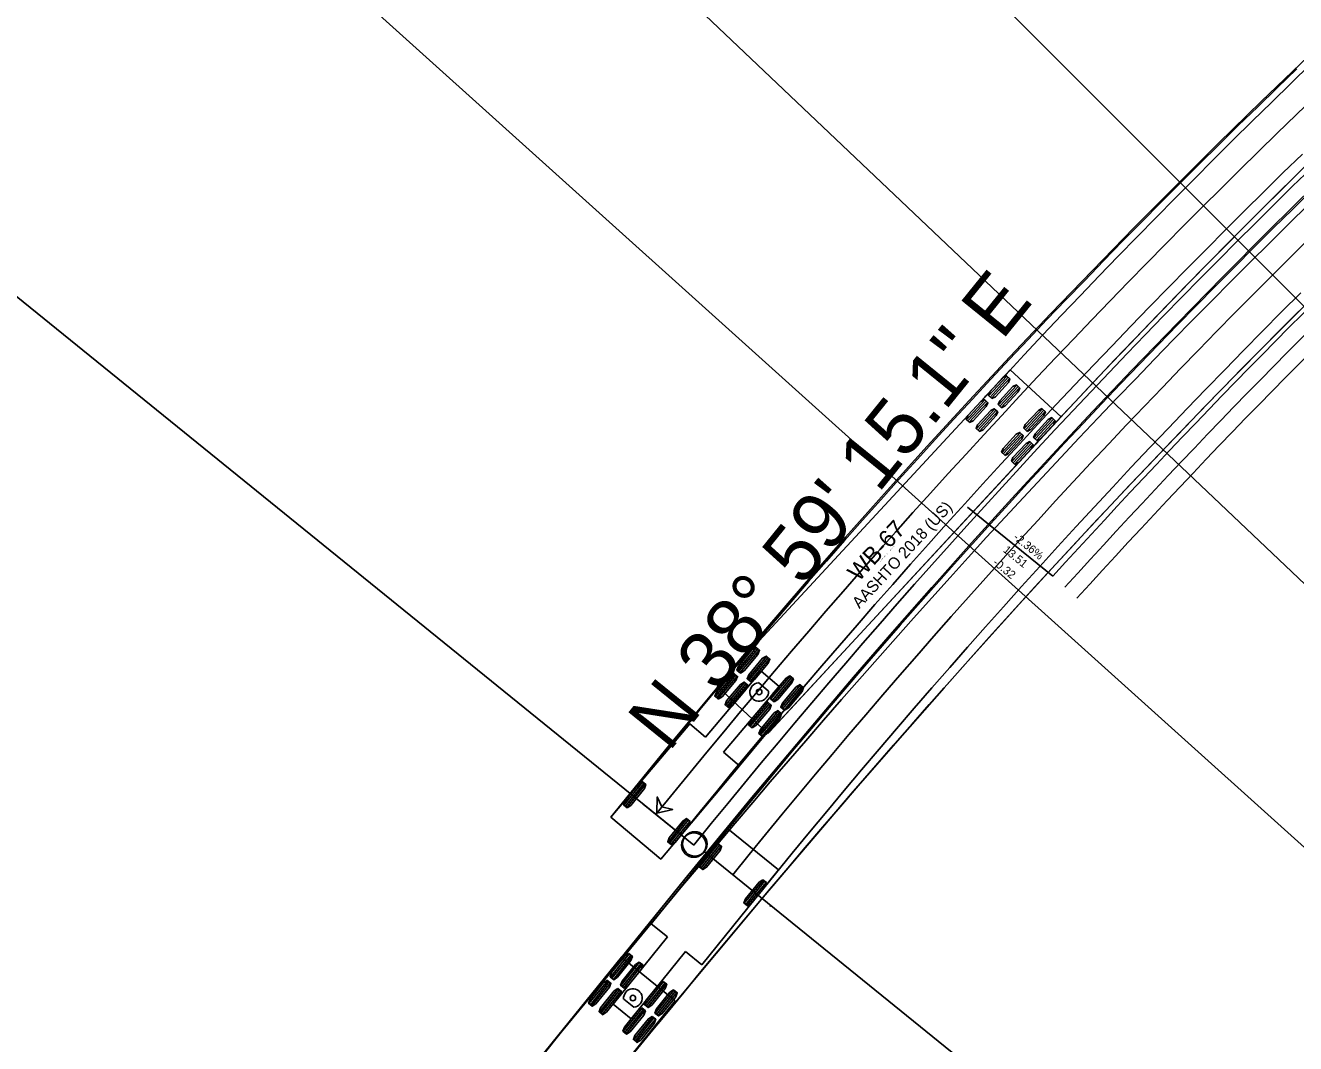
# Model space of a CAD drawing. Extents: x 2293233 to 2294507, y 892788 to 894229.
# Drawn here: x 2293388.7 to 2293544.7, y 893014 to 893139.1 of the extents above; entities that cross this region are included whole.
import ezdxf

# ---------------------------------------------------------------- set-up
doc = ezdxf.new("R2010")
doc.units = 0
for name, color, linetype in [('COGO Default Curve', 7, 'Continuous'), ('Default', 7, 'Continuous'), ('Prop EOT', 7, 'Continuous'), ('Prop Horizontal Alignment', 7, 'Continuous'), ('Prop Paved Shoulder', 7, 'Continuous'), ('Scratch_Level_4', 7, 'Continuous'), ('Scratch_Level_5', 7, 'Continuous'), ('Scratch_Level_6', 7, 'Continuous')]:
    doc.layers.add(name, color=color, linetype=linetype)

msp = doc.modelspace()

# ---------------------------------------------------------------- linework, layer by layer
at = {"layer": 'COGO Default Curve'}
for p, q in [((2293509.68, 893096.77), (2293473.68, 893057.88)), ((2293507.03, 893093.57), (2293509.27, 893095.99)), ((2293515.92, 893091), (2293509.68, 893096.77)), ((2293507.2, 893093.41), (2293509.44, 893095.84)), ((2293507.37, 893093.26), (2293509.61, 893095.68)), ((2293508.24, 893092.45), (2293510.48, 893094.87)), ((2293508.41, 893092.29), (2293510.65, 893094.72)), ((2293508.58, 893092.14), (2293510.82, 893094.56)), ((2293504.31, 893090.63), (2293506.55, 893093.06)), ((2293504.48, 893090.48), (2293506.72, 893092.9)), ((2293504.65, 893090.32), (2293506.89, 893092.75)), ((2293505.52, 893089.51), (2293507.76, 893091.94)), ((2293505.69, 893089.36), (2293507.93, 893091.78)), ((2293505.86, 893089.2), (2293508.1, 893091.62)), ((2293511.38, 893089.54), (2293513.63, 893091.96)), ((2293511.55, 893089.38), (2293513.79, 893091.81)), ((2293511.72, 893089.23), (2293513.96, 893091.65)), ((2293479.91, 893052.1), (2293515.92, 893091)), ((2293512.59, 893088.42), (2293514.84, 893090.84)), ((2293512.76, 893088.26), (2293515, 893090.68)), ((2293512.93, 893088.11), (2293515.17, 893090.53)), ((2293508.67, 893086.6), (2293510.91, 893089.03)), ((2293508.83, 893086.45), (2293511.08, 893088.87)), ((2293509, 893086.29), (2293511.24, 893088.71)), ((2293509.88, 893085.48), (2293512.12, 893087.9)), ((2293510.05, 893085.33), (2293512.29, 893087.75)), ((2293510.21, 893085.17), (2293512.46, 893087.59)), ((2293476.12, 893059.83), (2293478.49, 893062.63)), ((2293476.3, 893059.68), (2293478.66, 893062.48)), ((2293476.47, 893059.53), (2293478.84, 893062.33)), ((2293477.38, 893058.76), (2293479.75, 893061.57)), ((2293477.56, 893058.62), (2293479.92, 893061.42)), ((2293477.73, 893058.47), (2293480.1, 893061.27)), ((2293479.09, 893059.72), (2293472.25, 893051.62)), ((2293473.41, 893056.62), (2293475.78, 893059.42)), ((2293473.59, 893056.47), (2293475.95, 893059.27)), ((2293473.76, 893056.32), (2293476.13, 893059.13)), ((2293481.28, 893057.87), (2293479.09, 893059.72)), ((2293480.28, 893056.32), (2293482.64, 893059.13)), ((2293480.45, 893056.18), (2293482.82, 893058.98)), ((2293480.63, 893056.03), (2293482.99, 893058.83)), ((2293473.68, 893057.88), (2293479.91, 893052.1)), ((2293474.45, 893049.77), (2293481.28, 893057.87)), ((2293474.68, 893055.55), (2293477.04, 893058.36)), ((2293474.85, 893055.41), (2293477.22, 893058.21)), ((2293475.03, 893055.26), (2293477.39, 893058.06)), ((2293479.97, 893057.29), (2293478.74, 893058.33)), ((2293481.54, 893055.26), (2293483.9, 893058.06)), ((2293481.71, 893055.11), (2293484.08, 893057.91)), ((2293481.89, 893054.96), (2293484.25, 893057.77)), ((2293477.57, 893053.11), (2293479.93, 893055.92)), ((2293477.74, 893052.97), (2293480.11, 893055.77)), ((2293477.92, 893052.82), (2293480.28, 893055.62)), ((2293478.83, 893052.05), (2293481.19, 893054.85)), ((2293479, 893051.9), (2293481.37, 893054.7)), ((2293479.18, 893051.75), (2293481.54, 893054.56)), ((2293470.29, 893053.28), (2293460.62, 893041.81)), ((2293472.25, 893051.62), (2293470.29, 893053.28)), ((2293479.91, 893052.1), (2293479.91, 893052.1)), ((2293476.41, 893048.12), (2293474.45, 893049.77)), ((2293466.73, 893036.65), (2293476.41, 893048.12)), ((2293462.21, 893043.29), (2293464.52, 893046.14)), ((2293462.39, 893043.14), (2293464.7, 893045.99)), ((2293462.57, 893043), (2293464.87, 893045.85)), ((2293460.62, 893041.81), (2293466.73, 893036.65)), ((2293467.64, 893038.73), (2293469.94, 893041.58)), ((2293467.81, 893038.59), (2293470.12, 893041.44)), ((2293474.99, 893040.37), (2293465.55, 893028.71)), ((2293467.99, 893038.44), (2293470.3, 893041.29)), ((2293481.21, 893035.33), (2293474.99, 893040.37)), ((2293474.99, 893040.37), (2293474.99, 893040.37)), ((2293473.81, 893038.54), (2293471.5, 893035.69)), ((2293473.98, 893038.39), (2293471.68, 893035.54)), ((2293474.16, 893038.25), (2293471.85, 893035.4)), ((2293466.73, 893036.65), (2293466.73, 893036.65)), ((2293471.77, 893023.67), (2293481.21, 893035.33)), ((2293479.31, 893034.08), (2293477, 893031.23)), ((2293479.49, 893033.94), (2293477.18, 893031.09)), ((2293479.67, 893033.79), (2293477.36, 893030.94)), ((2293465.55, 893028.71), (2293467.55, 893027.09)), ((2293467.55, 893027.09), (2293460.88, 893018.85)), ((2293461.9, 893024.59), (2293428.55, 892983.39)), ((2293462.86, 893025.01), (2293460.55, 893022.16)), ((2293463.04, 893024.87), (2293460.73, 893022.02)), ((2293463.21, 893024.73), (2293460.91, 893021.88)), ((2293468.51, 893019.24), (2293461.9, 893024.59)), ((2293461.9, 893024.59), (2293461.9, 893024.59)), ((2293463.11, 893017.05), (2293469.78, 893025.29)), ((2293469.78, 893025.29), (2293471.77, 893023.67)), ((2293464.14, 893023.98), (2293461.83, 893021.13)), ((2293464.32, 893023.83), (2293462.01, 893020.98)), ((2293464.5, 893023.69), (2293462.19, 893020.84)), ((2293460.22, 893021.75), (2293457.91, 893018.9)), ((2293460.39, 893021.61), (2293458.09, 893018.76)), ((2293460.57, 893021.46), (2293458.26, 893018.61)), ((2293467.08, 893021.6), (2293464.77, 893018.75)), ((2293467.26, 893021.45), (2293464.95, 893018.6)), ((2293467.44, 893021.31), (2293465.13, 893018.46)), ((2293461.5, 893020.71), (2293459.19, 893017.86)), ((2293461.68, 893020.57), (2293459.37, 893017.72)), ((2293461.85, 893020.42), (2293459.55, 893017.57)), ((2293468.36, 893020.56), (2293466.06, 893017.71)), ((2293468.54, 893020.41), (2293466.23, 893017.56)), ((2293468.72, 893020.27), (2293466.41, 893017.42)), ((2293435.16, 892978.05), (2293468.51, 893019.24)), ((2293460.88, 893018.85), (2293463.11, 893017.05)), ((2293464.44, 893018.33), (2293462.13, 893015.48)), ((2293462.18, 893019.46), (2293463.43, 893018.45)), ((2293464.62, 893018.19), (2293462.31, 893015.34)), ((2293464.79, 893018.04), (2293462.49, 893015.19)), ((2293465.72, 893017.29), (2293463.41, 893014.44)), ((2293465.9, 893017.15), (2293463.59, 893014.3)), ((2293466.08, 893017), (2293463.77, 893014.15))]:
    msp.add_line(p, q, dxfattribs=at)
for points in [[(2293545.92, 893121.77), (2293541.18, 893117.08), (2293536.48, 893112.36), (2293531.8, 893107.6), (2293527.16, 893102.82), (2293522.55, 893098.01), (2293518.19, 893093.41), (2293513.42, 893088.3), (2293480.12, 893052.32), (2293479.78, 893052.17), (2293476.37, 893048.07), (2293466.73, 893036.65), (2293460.62, 893041.81), (2293462.02, 893043.56), (2293467.91, 893050.79), (2293473.66, 893057.7), (2293473.8, 893058.02), (2293479.39, 893064.63), (2293484.4, 893070.43), (2293489.44, 893076.2), (2293494.54, 893081.92), (2293499.46, 893087.36), (2293504.64, 893093), (2293509.64, 893098.36), (2293514.68, 893103.68), (2293519.77, 893108.97), (2293524.89, 893114.21), (2293530.06, 893119.42), (2293535.27, 893124.58), (2293540.51, 893129.71), (2293548.21, 893137.09)], [(2293544.9, 893133.73), (2293542.49, 893131.41), (2293540.09, 893129.08), (2293537.69, 893126.75), (2293535.31, 893124.4), (2293532.93, 893122.05), (2293530.56, 893119.69), (2293528.19, 893117.32), (2293525.84, 893114.94), (2293523.49, 893112.55), (2293521.16, 893110.16), (2293518.83, 893107.75), (2293516.51, 893105.34), (2293514.19, 893102.92), (2293511.89, 893100.49), (2293509.6, 893098.06), (2293507.31, 893095.62), (2293505.03, 893093.16), (2293502.76, 893090.7), (2293500.5, 893088.24), (2293498.25, 893085.76), (2293496, 893083.28), (2293493.77, 893080.79), (2293491.54, 893078.29), (2293489.32, 893075.78), (2293487.11, 893073.27), (2293484.91, 893070.75), (2293482.72, 893068.22), (2293480.54, 893065.68), (2293478.36, 893063.14), (2293476.2, 893060.59), (2293474.04, 893058.03), (2293471.9, 893055.46), (2293469.76, 893052.88), (2293467.63, 893050.3), (2293465.51, 893047.71), (2293463.4, 893045.12), (2293463.19, 893044.86)], [(2293546.6, 893134.31), (2293544.2, 893131.98), (2293541.81, 893129.65), (2293539.43, 893127.3), (2293537.05, 893124.95), (2293534.68, 893122.6), (2293532.32, 893120.23), (2293529.96, 893117.86), (2293527.62, 893115.48), (2293525.28, 893113.09), (2293522.95, 893110.7), (2293520.62, 893108.29), (2293518.31, 893105.88), (2293516, 893103.46), (2293513.7, 893101.04), (2293511.41, 893098.6), (2293509.13, 893096.16), (2293506.85, 893093.71), (2293506.62, 893093.47)], [(2293545.58, 893123.26), (2293543.2, 893120.95), (2293540.83, 893118.62), (2293538.48, 893116.28), (2293536.12, 893113.94), (2293533.78, 893111.59), (2293531.45, 893109.23), (2293529.12, 893106.86), (2293526.8, 893104.49), (2293524.49, 893102.1), (2293522.19, 893099.71), (2293519.9, 893097.31), (2293517.62, 893094.91), (2293515.34, 893092.49), (2293513.07, 893090.07), (2293510.81, 893087.64), (2293508.56, 893085.2), (2293506.32, 893082.75), (2293504.09, 893080.3), (2293501.86, 893077.83), (2293499.64, 893075.36), (2293497.44, 893072.88), (2293495.24, 893070.4), (2293493.05, 893067.91), (2293490.87, 893065.4), (2293488.69, 893062.9), (2293486.53, 893060.38), (2293484.37, 893057.86), (2293482.23, 893055.33), (2293480.09, 893052.79), (2293477.96, 893050.24), (2293475.84, 893047.69), (2293473.73, 893045.13), (2293471.63, 893042.56), (2293469.53, 893039.98), (2293469.32, 893039.73)], [(2293545.39, 893121.25), (2293543.04, 893118.92), (2293540.68, 893116.58), (2293538.34, 893114.23), (2293536.01, 893111.88), (2293533.68, 893109.52), (2293531.36, 893107.15), (2293529.05, 893104.78), (2293526.74, 893102.39), (2293524.45, 893100), (2293522.16, 893097.6), (2293519.88, 893095.2), (2293517.61, 893092.79), (2293515.34, 893090.37), (2293513.09, 893087.94), (2293512.86, 893087.69)], [(2293429.41, 892984.45), (2293469.68, 893034.18), (2293477.94, 893044.22), (2293485.65, 893053.41), (2293490.41, 893058.99), (2293495.21, 893064.53), (2293500.06, 893070.03), (2293504.94, 893075.5), (2293509.87, 893080.93), (2293514.83, 893086.32), (2293519.84, 893091.67), (2293524.66, 893096.74), (2293530.22, 893102.5), (2293535.82, 893108.2), (2293541.47, 893113.86), (2293547.17, 893119.47)], [(2293472.47, 893037.26), (2293474.58, 893039.85), (2293476.69, 893042.43), (2293478.82, 893045.01), (2293480.95, 893047.58), (2293483.1, 893050.15), (2293485.25, 893052.71), (2293487.41, 893055.26), (2293489.59, 893057.8), (2293491.77, 893060.34), (2293493.96, 893062.86), (2293496.16, 893065.39), (2293498.37, 893067.9), (2293500.59, 893070.4), (2293502.81, 893072.9), (2293505.05, 893075.39), (2293507.29, 893077.88), (2293509.55, 893080.35), (2293511.81, 893082.82), (2293514.08, 893085.28), (2293516.36, 893087.73), (2293518.65, 893090.17), (2293520.95, 893092.61), (2293523.25, 893095.03), (2293525.57, 893097.45), (2293527.89, 893099.86), (2293530.22, 893102.27), (2293532.56, 893104.66), (2293534.91, 893107.05), (2293537.27, 893109.42), (2293539.63, 893111.79), (2293542.01, 893114.15), (2293544.39, 893116.51), (2293546.78, 893118.85)], [(2293452.4, 893012.79), (2293454.51, 893015.38), (2293456.63, 893017.96), (2293458.75, 893020.54), (2293460.87, 893023.11), (2293463, 893025.69), (2293465.13, 893028.26), (2293467.27, 893030.83), (2293469.41, 893033.39), (2293471.56, 893035.95), (2293473.71, 893038.5), (2293475.87, 893041.05), (2293478.03, 893043.6), (2293480.2, 893046.14), (2293482.38, 893048.67), (2293484.56, 893051.2), (2293486.75, 893053.73), (2293488.95, 893056.25), (2293491.15, 893058.76), (2293493.36, 893061.27), (2293495.58, 893063.77), (2293497.81, 893066.26), (2293500.04, 893068.75), (2293502.28, 893071.23), (2293504.53, 893073.71), (2293506.78, 893076.18), (2293509.04, 893078.64), (2293511.31, 893081.09), (2293513.59, 893083.54), (2293515.88, 893085.98), (2293518.17, 893088.41), (2293520.47, 893090.84), (2293522.78, 893093.26), (2293525.1, 893095.67), (2293527.42, 893098.07), (2293529.75, 893100.47), (2293532.09, 893102.86), (2293534.44, 893105.24), (2293536.8, 893107.61), (2293539.16, 893109.98), (2293541.54, 893112.33), (2293543.92, 893114.68), (2293546.3, 893117.02)], [(2293478.69, 893032.22), (2293480.79, 893034.81), (2293482.9, 893037.38), (2293485.01, 893039.95), (2293487.14, 893042.51), (2293489.27, 893045.06), (2293491.41, 893047.6), (2293493.56, 893050.14), (2293495.72, 893052.67), (2293497.89, 893055.18), (2293500.06, 893057.69), (2293502.25, 893060.2), (2293504.44, 893062.69), (2293506.64, 893065.18), (2293508.85, 893067.66), (2293511.07, 893070.13), (2293513.3, 893072.59), (2293515.53, 893075.04), (2293517.78, 893077.49), (2293520.03, 893079.93), (2293522.29, 893082.36), (2293524.56, 893084.78), (2293526.84, 893087.2), (2293529.13, 893089.6), (2293531.42, 893092), (2293533.73, 893094.39), (2293536.04, 893096.77), (2293538.36, 893099.15), (2293540.69, 893101.51), (2293543.03, 893103.87), (2293545.38, 893106.22)], [(2293545.7, 893104.49), (2293540.52, 893099.3), (2293535.15, 893093.83), (2293529.59, 893088.08), (2293523.84, 893082.04), (2293518.37, 893076.2), (2293512.72, 893070.08), (2293507.11, 893063.91), (2293501.56, 893057.69), (2293495.82, 893051.19), (2293490.13, 893044.65), (2293484.71, 893038.33), (2293479.32, 893031.97), (2293473.54, 893025.07), (2293467.58, 893017.89), (2293461.65, 893010.68), (2293455.12, 893002.67), (2293435.78, 892978.82), (2293435.35, 892978.31), (2293435.16, 892978.05), (2293428.55, 892983.39), (2293429.41, 892984.45)], [(2293463.2, 893012.57), (2293465.31, 893015.14), (2293467.43, 893017.7), (2293469.55, 893020.27), (2293471.67, 893022.83), (2293473.8, 893025.38), (2293475.93, 893027.93), (2293478.06, 893030.48), (2293480.2, 893033.02), (2293482.35, 893035.55), (2293484.5, 893038.09), (2293486.66, 893040.61), (2293488.82, 893043.13), (2293490.99, 893045.64), (2293493.17, 893048.15), (2293495.35, 893050.65), (2293497.54, 893053.15), (2293499.73, 893055.64), (2293501.93, 893058.12), (2293504.14, 893060.6), (2293506.36, 893063.07), (2293508.58, 893065.53), (2293510.81, 893067.99), (2293513.05, 893070.44), (2293515.29, 893072.88), (2293517.55, 893075.31), (2293519.81, 893077.74), (2293522.07, 893080.16), (2293524.35, 893082.58), (2293526.63, 893084.98), (2293528.92, 893087.38), (2293531.22, 893089.77), (2293533.52, 893092.16), (2293535.84, 893094.53), (2293538.16, 893096.9), (2293540.48, 893099.26), (2293542.82, 893101.61), (2293545.16, 893103.96)], [(2293466.26, 893042.29), (2293468.2, 893042.76), (2293466.88, 893043.07), (2293466.31, 893044.29), (2293466.26, 893042.29)]]:
    msp.add_lwpolyline(points, dxfattribs=at)
for points in [[(2293507.41, 893093.22), (2293506.99, 893093.61), (2293507.18, 893094.06), (2293508.79, 893095.81), (2293509.23, 893096.03), (2293509.65, 893095.64), (2293509.46, 893095.19), (2293507.85, 893093.44)], [(2293508.62, 893092.1), (2293508.2, 893092.49), (2293508.39, 893092.94), (2293510, 893094.69), (2293510.44, 893094.91), (2293510.86, 893094.52), (2293510.67, 893094.06), (2293509.06, 893092.32)], [(2293504.69, 893090.28), (2293504.27, 893090.67), (2293504.46, 893091.13), (2293506.07, 893092.87), (2293506.51, 893093.1), (2293506.93, 893092.71), (2293506.74, 893092.25), (2293505.13, 893090.51)], [(2293505.9, 893089.16), (2293505.48, 893089.55), (2293505.67, 893090.01), (2293507.28, 893091.75), (2293507.72, 893091.97), (2293508.14, 893091.59), (2293507.96, 893091.13), (2293506.34, 893089.39)], [(2293511.76, 893089.19), (2293511.34, 893089.58), (2293511.53, 893090.03), (2293513.14, 893091.78), (2293513.58, 893092), (2293514, 893091.61), (2293513.82, 893091.16), (2293512.2, 893089.41)], [(2293512.97, 893088.07), (2293512.55, 893088.46), (2293512.74, 893088.91), (2293514.35, 893090.66), (2293514.79, 893090.88), (2293515.21, 893090.49), (2293515.03, 893090.03), (2293513.41, 893088.29)], [(2293509.04, 893086.25), (2293508.62, 893086.64), (2293508.81, 893087.1), (2293510.43, 893088.84), (2293510.87, 893089.06), (2293511.29, 893088.68), (2293511.1, 893088.22), (2293509.48, 893086.48)], [(2293510.26, 893085.13), (2293509.84, 893085.52), (2293510.02, 893085.98), (2293511.64, 893087.72), (2293512.08, 893087.94), (2293512.5, 893087.55), (2293512.31, 893087.1), (2293510.7, 893085.36)], [(2293476.52, 893059.5), (2293476.08, 893059.87), (2293476.28, 893060.37), (2293477.98, 893062.39), (2293478.44, 893062.67), (2293478.88, 893062.3), (2293478.68, 893061.79), (2293476.98, 893059.78)], [(2293477.78, 893058.43), (2293477.34, 893058.8), (2293477.54, 893059.3), (2293479.24, 893061.32), (2293479.71, 893061.6), (2293480.14, 893061.23), (2293479.94, 893060.73), (2293478.24, 893058.71)], [(2293473.81, 893056.29), (2293473.37, 893056.66), (2293473.57, 893057.16), (2293475.27, 893059.18), (2293475.74, 893059.46), (2293476.17, 893059.09), (2293475.97, 893058.59), (2293474.27, 893056.57)], [(2293480.67, 893055.99), (2293480.23, 893056.36), (2293480.43, 893056.86), (2293482.13, 893058.88), (2293482.6, 893059.16), (2293483.03, 893058.79), (2293482.83, 893058.29), (2293481.13, 893056.27)], [(2293475.07, 893055.22), (2293474.63, 893055.59), (2293474.83, 893056.09), (2293476.53, 893058.11), (2293477, 893058.39), (2293477.43, 893058.02), (2293477.23, 893057.52), (2293475.53, 893055.5)], [(2293481.93, 893054.93), (2293481.49, 893055.3), (2293481.69, 893055.8), (2293483.39, 893057.82), (2293483.86, 893058.1), (2293484.29, 893057.73), (2293484.1, 893057.23), (2293482.39, 893055.21)], [(2293477.96, 893052.78), (2293477.52, 893053.15), (2293477.72, 893053.65), (2293479.43, 893055.67), (2293479.89, 893055.95), (2293480.32, 893055.58), (2293480.13, 893055.08), (2293478.42, 893053.06)], [(2293479.22, 893051.72), (2293478.78, 893052.09), (2293478.98, 893052.59), (2293480.69, 893054.61), (2293481.15, 893054.89), (2293481.59, 893054.52), (2293481.39, 893054.02), (2293479.68, 893052)], [(2293462.61, 893042.96), (2293462.17, 893043.32), (2293462.36, 893043.83), (2293464.02, 893045.88), (2293464.47, 893046.17), (2293464.92, 893045.81), (2293464.73, 893045.31), (2293463.07, 893043.25)], [(2293466.26, 893042.29), (2293468.2, 893042.76), (2293466.88, 893043.07), (2293466.31, 893044.29)], [(2293468.04, 893038.41), (2293467.59, 893038.77), (2293467.78, 893039.28), (2293469.44, 893041.33), (2293469.9, 893041.62), (2293470.34, 893041.26), (2293470.15, 893040.75), (2293468.49, 893038.7)], [(2293473.76, 893038.57), (2293474.21, 893038.21), (2293474.02, 893037.71), (2293472.36, 893035.66), (2293471.9, 893035.36), (2293471.45, 893035.72), (2293471.64, 893036.23), (2293473.3, 893038.28)], [(2293479.27, 893034.12), (2293479.71, 893033.76), (2293479.52, 893033.25), (2293477.86, 893031.2), (2293477.4, 893030.91), (2293476.96, 893031.27), (2293477.15, 893031.78), (2293478.81, 893033.83)], [(2293462.81, 893025.05), (2293463.26, 893024.69), (2293463.07, 893024.18), (2293461.41, 893022.13), (2293460.95, 893021.84), (2293460.51, 893022.2), (2293460.7, 893022.71), (2293462.36, 893024.76)], [(2293464.1, 893024.01), (2293464.54, 893023.65), (2293464.35, 893023.14), (2293462.69, 893021.09), (2293462.23, 893020.8), (2293461.79, 893021.16), (2293461.98, 893021.67), (2293463.64, 893023.72)], [(2293460.17, 893021.79), (2293460.62, 893021.43), (2293460.43, 893020.92), (2293458.77, 893018.87), (2293458.31, 893018.58), (2293457.86, 893018.94), (2293458.05, 893019.44), (2293459.71, 893021.49)], [(2293467.04, 893021.63), (2293467.48, 893021.27), (2293467.29, 893020.76), (2293465.63, 893018.71), (2293465.17, 893018.42), (2293464.73, 893018.78), (2293464.92, 893019.29), (2293466.58, 893021.34)], [(2293461.45, 893020.75), (2293461.9, 893020.39), (2293461.71, 893019.88), (2293460.05, 893017.83), (2293459.59, 893017.54), (2293459.15, 893017.9), (2293459.34, 893018.4), (2293461, 893020.46)], [(2293468.32, 893020.59), (2293468.76, 893020.23), (2293468.57, 893019.73), (2293466.91, 893017.67), (2293466.46, 893017.38), (2293466.01, 893017.74), (2293466.2, 893018.25), (2293467.86, 893020.3)], [(2293464.39, 893018.37), (2293464.84, 893018.01), (2293464.65, 893017.5), (2293462.99, 893015.45), (2293462.53, 893015.16), (2293462.09, 893015.52), (2293462.28, 893016.02), (2293463.94, 893018.08)], [(2293465.68, 893017.33), (2293466.12, 893016.97), (2293465.93, 893016.46), (2293464.27, 893014.41), (2293463.81, 893014.12), (2293463.37, 893014.48), (2293463.56, 893014.99), (2293465.22, 893017.04)]]:
    msp.add_lwpolyline(points, close=True, dxfattribs=at)
for centre, radius in [((2293506.62, 893093.47), 0.0417), ((2293512.86, 893087.69), 0.0417), ((2293478.83, 893057.19), 0.34), ((2293463.19, 893044.86), 0.0417), ((2293466.26, 893042.29), 0.0417), ((2293469.32, 893039.73), 0.0417), ((2293472.47, 893037.26), 0.0417), ((2293478.69, 893032.22), 0.0417), ((2293463.31, 893019.58), 0.34)]:
    msp.add_circle(centre, radius, dxfattribs=at)
for centre, radius, start, end in [((2294209.34, 892440.82), 956, 128.6085, 141.01247), ((2294209.34, 892440.82), 944, 128.6085, 141.01247), ((2293478.83, 893057.19), 1.14, 94.8338, 4.8338), ((2293463.31, 893019.58), 1.14, 276.0125, 186.0125)]:
    msp.add_arc(centre, radius, start, end, dxfattribs=at)
at = {"layer": 'Default'}
msp.add_line((2293504.41, 893079.89), (2293514.91, 893071.39), dxfattribs=at)
at = {"layer": 'Prop EOT'}
msp.add_line((2293480.13, 893030.82), (2293480.25, 893030.97), dxfattribs=at)
msp.add_line((2293480.13, 893030.82), (2293480.25, 893030.97), dxfattribs=at)
msp.add_arc((2294209.34, 892440.82), 938, 128.6085, 137.75907, dxfattribs=at)
at = {"layer": 'Prop Horizontal Alignment'}
for p, q in [((2293469.64, 893039.32), (2293257.05, 893211.39)), ((2293537.68, 893112.66), (2293534.14, 893116.2)), ((2293470.8, 893038.37), (2293464.59, 893043.41)), ((2293470.8, 893038.37), (2293470.92, 893038.52)), ((2293470.8, 893038.37), (2293470.92, 893038.52)), ((2293472.08, 893037.57), (2293684.67, 892865.5))]:
    msp.add_line(p, q, dxfattribs=at)
for centre in [(2293470.8, 893038.37), (2293470.92, 893038.52)]:
    msp.add_circle(centre, 1.5, dxfattribs=at)
msp.add_arc((2294209.34, 892440.82), 950, 128.6085, 141.01247, dxfattribs=at)
msp.add_arc((2294209.34, 892440.82), 950, 128.6085, 141.01247, dxfattribs=at)
at = {"layer": 'Prop Paved Shoulder'}
msp.add_arc((2294209.34, 892440.82), 936, 128.6085, 137.75907, dxfattribs=at)
at = {"layer": 'Scratch_Level_4'}
for p, q in [((2293431.62, 893218.74), (2293643.73, 893006.58)), ((2293411.42, 893198.01), (2293629.04, 892991.5)), ((2293391.78, 893176.75), (2293614.75, 892976.04))]:
    msp.add_line(p, q, dxfattribs=at)
at = {"layer": 'Scratch_Level_5'}
msp.add_arc((2294209.34, 892440.82), 934, 128.6085, 137.75907, dxfattribs=at)
at = {"layer": 'Scratch_Level_6'}
msp.add_line((2293504.41, 893079.89), (2293514.91, 893071.39), dxfattribs=at)

# ---------------------------------------------------------------- texts
at = {"layer": 'COGO Default Curve'}
for s, height, p in [('AASHTO 2018 (US)', 1.4167, (2293491.15, 893067.36)), ('WB-67', 2.125, (2293491.06, 893070.65)), ('(c) 2022 Transoft Solutions, Inc. All rights reserved.', 0.085, (2293493.65, 893073.13))]:
    msp.add_text(s, height=height, rotation=47.2087, dxfattribs=at).set_placement(p)
at = {"layer": 'Default'}
for s, p in [('-2.36%', (2293509.98, 893076.03)), ('13.51', (2293508.72, 893074.48)), ('-0.32', (2293507.46, 893072.92))]:
    msp.add_text(s, height=1, rotation=321.0125, dxfattribs=at).set_placement(p)
at = {"layer": 'Prop Horizontal Alignment'}
msp.add_text('N 38%%d 59\' 15.1" E', height=7, rotation=51.0125, dxfattribs=at).set_placement((2293467.72, 893049.69))

doc.saveas('drawing.dxf')
